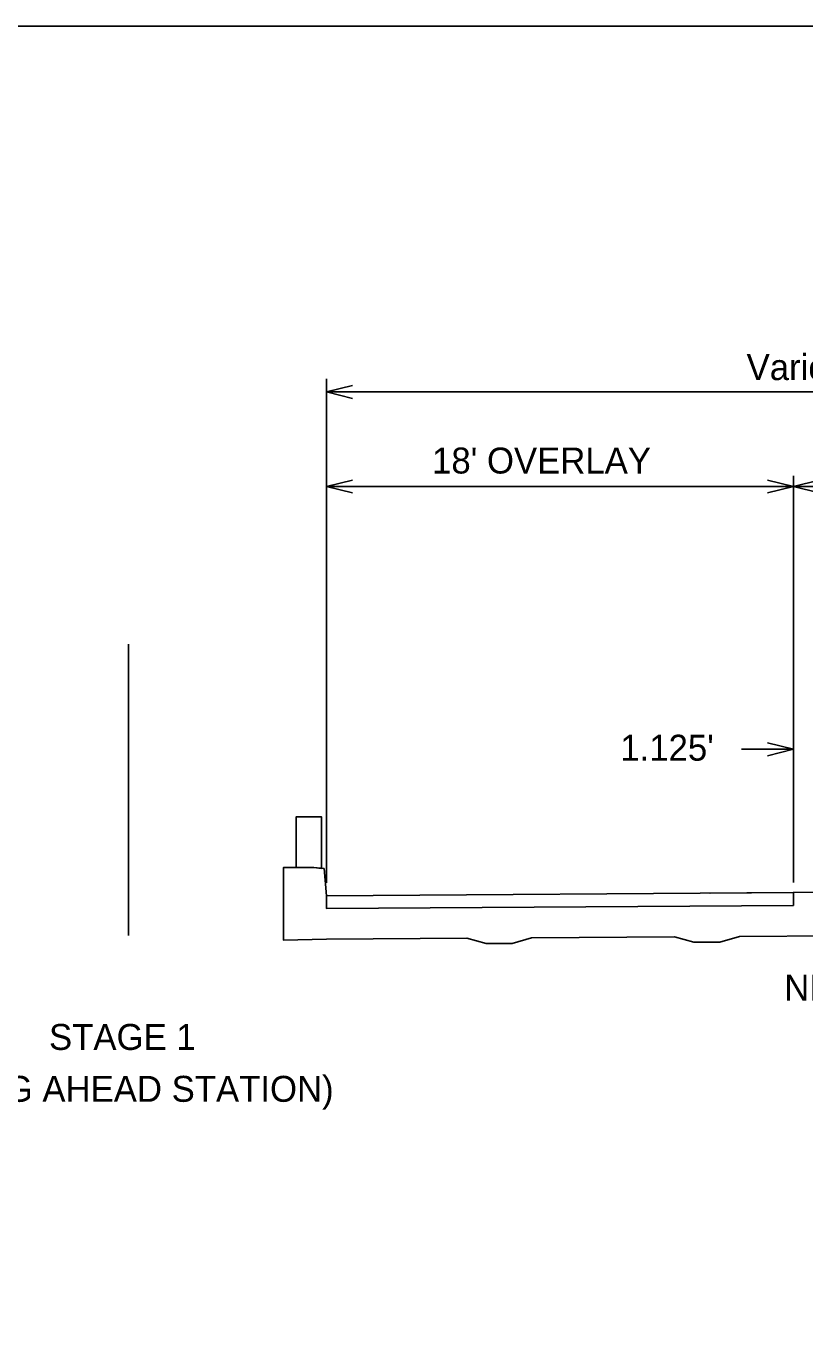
# Model space of a CAD drawing. Extents: x 10133 to 81668, y 7924 to 11018.
# Drawn here: x 11636 to 12236, y 8934 to 9944 of the extents above; entities that cross this region are included whole.
import ezdxf

# ---------------------------------------------------------------- set-up
doc = ezdxf.new("R2010")
doc.units = 0
for name, color, linetype in [('brgConcrete', 7, 'Continuous'), ('brgConstructionLines', 7, 'Continuous'), ('brgDimensionLines', 7, 'Continuous'), ('brgPreStructureExisting', 7, 'Continuous'), ('dsnStdLineDrawingWt2', 7, 'Continuous'), ('SheetBorder', 7, 'Continuous')]:
    doc.layers.add(name, color=color, linetype=linetype)

msp = doc.modelspace()

# ---------------------------------------------------------------- linework, layer by layer
at = {"layer": 'brgConcrete'}
for p, q in [((11867, 9273.9), (12226.7, 9276.3)), ((11867, 9268.7), (11867, 9273.9)), ((12226.7, 9276.3), (12226.8, 9266.5)), ((11867, 9268.7), (11867, 9264.1)), ((11867, 9264.1), (12226.7, 9266.5)), ((11867, 9264.1), (12226.7, 9266.5))]:
    msp.add_line(p, q, dxfattribs=at)
at = {"layer": 'brgConstructionLines'}
msp.add_circle((12162.6, 9276), 0.104, dxfattribs=at)
at = {"layer": 'brgDimensionLines'}
msp.add_line((11714.6, 9243.3), (11714.6, 9467.8), dxfattribs=at)
at = {"layer": 'brgPreStructureExisting'}
for p, q in [((11843.7, 9295.6), (11857.3, 9295.6)), ((11857.3, 9295.6), (11863.2, 9295)), ((12162.6, 9275.9), (12306.8, 9276.9)), ((12025.1, 9241.5), (12135.1, 9242.2)), ((12185.1, 9242.5), (12295.1, 9243.3)), ((11867, 9240.4), (11975.1, 9241.1))]:
    msp.add_line(p, q, dxfattribs=at)
for points in [[(11843.7, 9295.6), (11843.7, 9334.8), (11863.2, 9334.8), (11863.2, 9295)], [(11863.2, 9295), (11863.2, 9334.8), (11843.7, 9334.8), (11843.7, 9295.6)], [(11833.9, 9274.8), (11833.9, 9295.6), (11857.3, 9295.6), (11865.2, 9294.8), (11867, 9273.9)], [(11833.9, 9274.8), (11833.9, 9239.8), (11867, 9240.4)], [(12135.1, 9242.2), (12150.1, 9238.2), (12170.1, 9238.2), (12185.1, 9242.5)], [(11975.1, 9241.1), (11990.1, 9237.1), (12010.1, 9237.1), (12025.1, 9241.5)]]:
    msp.add_lwpolyline(points, dxfattribs=at)
msp.add_lwpolyline([(12226.7, 9276.3), (12226.7, 9266.5), (11867, 9264.1), (11867, 9273.9)], close=True, dxfattribs=at)
at = {"layer": 'dsnStdLineDrawingWt2'}
for p, q in [((11867, 9283.9), (11867, 9672.2)), ((11867, 9662.2), (12907, 9662.2)), ((11867, 9283.9), (11867, 9599.3)), ((12226.7, 9284.1), (12226.7, 9597.5)), ((11867, 9589.3), (12226.8, 9589.3)), ((12226.8, 9589.3), (12907, 9589.3)), ((12186.7, 9386.8), (12226.7, 9386.8))]:
    msp.add_line(p, q, dxfattribs=at)
for points in [[(11887, 9657.2), (11867, 9662.2), (11887, 9667.2)], [(11887, 9584.3), (11867, 9589.3), (11887, 9594.3)], [(12206.7, 9594.3), (12226.7, 9589.3), (12206.7, 9584.3)], [(12246.7, 9584.3), (12226.7, 9589.3), (12246.7, 9594.3)], [(12206.7, 9391.8), (12226.7, 9386.8), (12206.7, 9381.8)]]:
    msp.add_lwpolyline(points, dxfattribs=at)
at = {"layer": 'SheetBorder'}
msp.add_lwpolyline([(10132.5, 9944), (13267.5, 9944), (13267.5, 7924), (10132.5, 7924)], close=True, dxfattribs=at)

# ---------------------------------------------------------------- texts
at = {"layer": 'dsnStdLineDrawingWt2'}
for s, p in [("Varies: 62.5' to 57.17'", (12190.7, 9671.3)), ("18' OVERLAY", (11948.4, 9599.3)), ("1.125'", (12093.4, 9378)), ('NB', (12219.7, 9193)), ('STAGE 1', (11653.3, 9155.1)), ('(LOOKING AHEAD STATION)', (11510, 9115.1))]:
    msp.add_text(s, height=20, dxfattribs=at).set_placement(p)

doc.saveas('drawing.dxf')
